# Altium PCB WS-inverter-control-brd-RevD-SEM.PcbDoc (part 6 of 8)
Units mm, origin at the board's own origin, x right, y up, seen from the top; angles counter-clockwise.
Board outline 270 x 105.92 mm, 6 copper layers (Top Layer, Int1 (Sign), Int2 (PWR), Int3 (GND), Int4 (Sign), Bottom Layer), stack 1.509 mm thick; 709 components, 375 nets, 2377 pads, 1332 vias.
Unrouted connection lines stored in the file: 55.
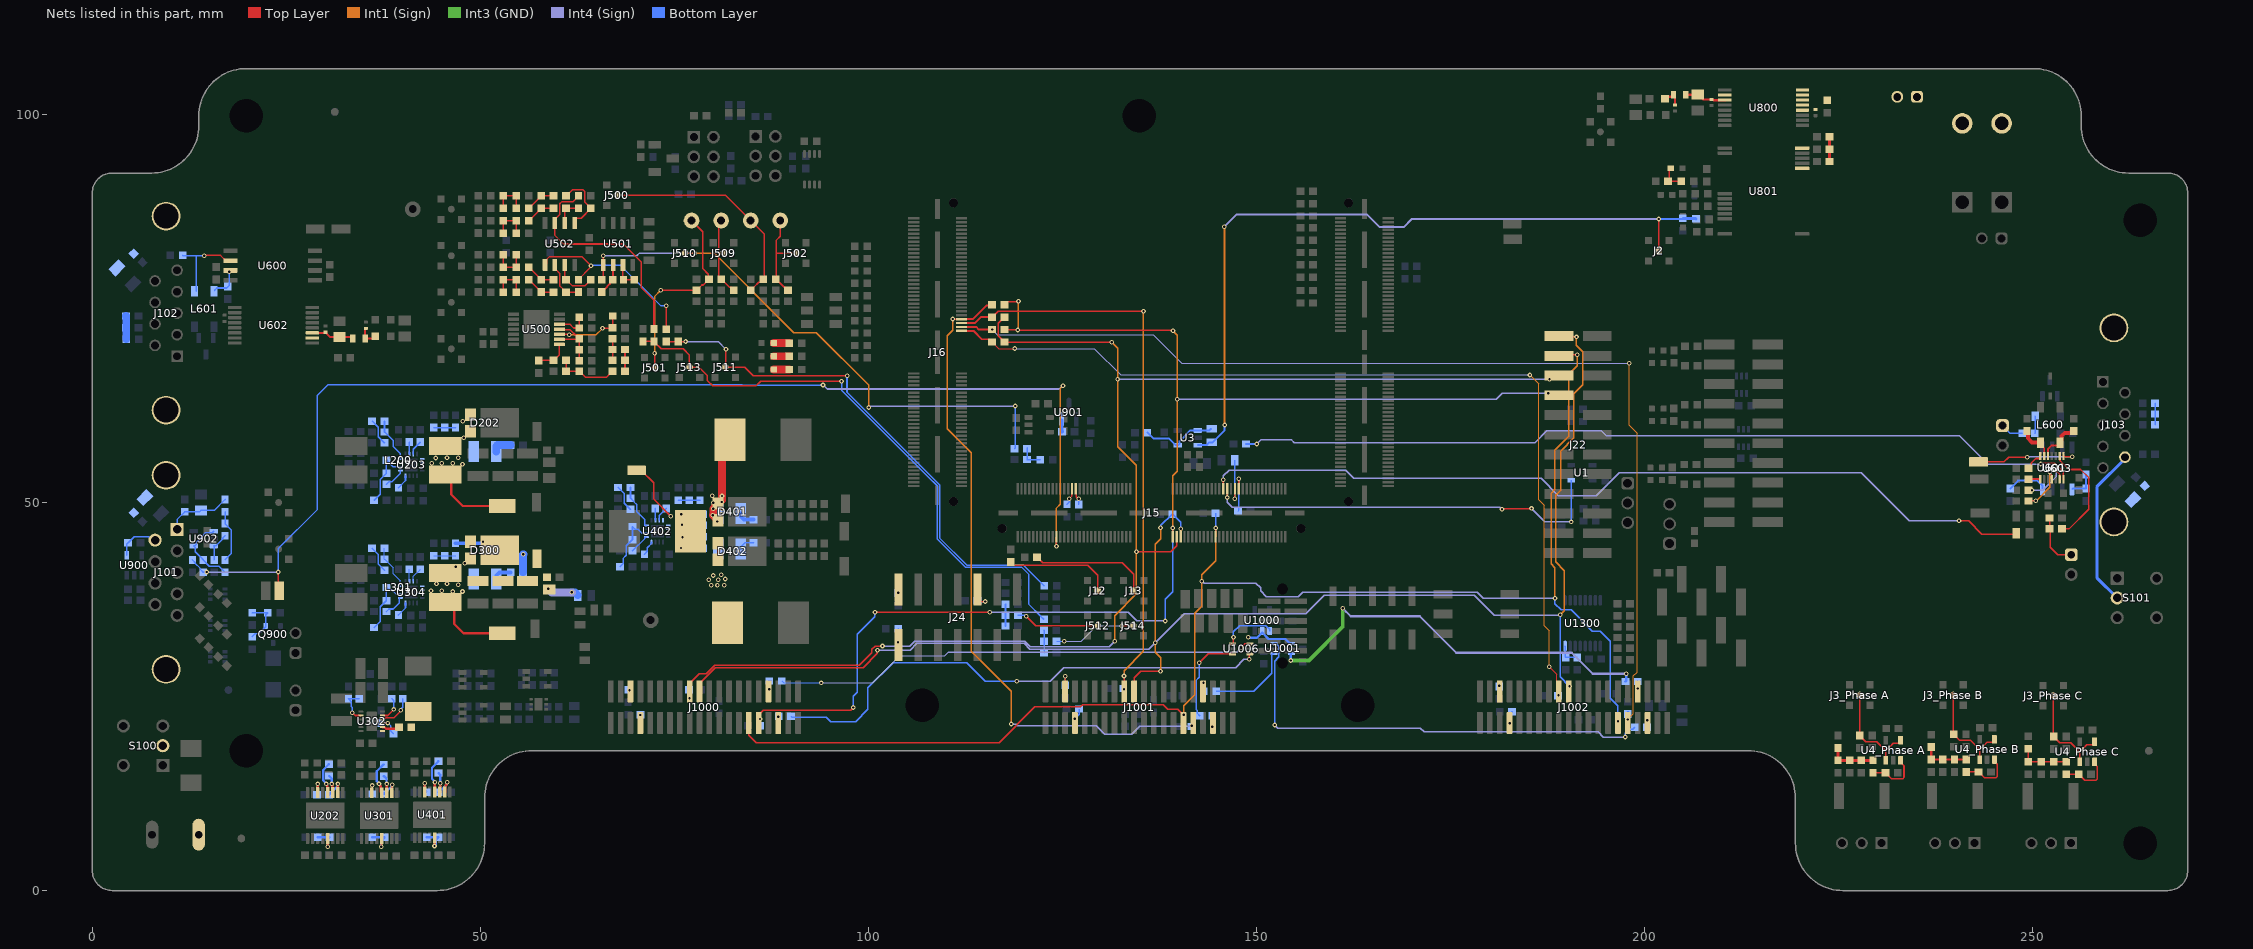
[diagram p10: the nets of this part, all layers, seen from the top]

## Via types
v1: diameter 0.6, hole 0.3, Top Layer to Bottom Layer, tented both sides, 1302 vias
v2: diameter 0.5, hole 0.2, Top Layer to Bottom Layer, 17 vias
v3: diameter 0.6, hole 0.3, Top Layer to Bottom Layer, 12 vias
v4: diameter 0.8, hole 0.5, Top Layer to Bottom Layer, tented both sides, 1 vias

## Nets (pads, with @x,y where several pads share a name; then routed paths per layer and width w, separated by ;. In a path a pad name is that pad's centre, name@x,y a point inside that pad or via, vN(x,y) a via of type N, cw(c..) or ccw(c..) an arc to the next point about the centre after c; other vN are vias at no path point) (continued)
MOTOR_TEMP: C908.1 J15.99 R904.1 TP900.1 | length 158.5
  Top Layer w0.18: v1(124.233,44.346) J15.99@124.233,45.585
  Top Layer w0.2: v1(23.966,41.034) 23.966,38.763 TP900.1@24.093,38.636
  Int1 (Sign) w0.2: v1(124.233,44.346) 124.233,49.278 124.733,49.778 124.733,64.681 v1(125.078,65.026)
  Int4 (Sign) w0.2: v1(14.725,41.034) v1(23.966,41.034) ; v1(94.143,65.136) 94.195,65.136 94.704,64.627 124.57,64.627 124.97,65.026 v1(125.078,65.026)
  Bottom Layer w0.2: C908.1@12.9,42.6 13.275,42.225 13.275,42.143 13.925,41.493 13.925,41.375 R904.1@14.3,41 14.334,41.034 v1(14.725,41.034) ; v1(23.966,41.034) 23.966,44.059 28.953,49.046 28.953,63.758 29.043,63.848 29.043,63.861 30.331,65.148 83.764,65.148 83.776,65.136 v1(94.143,65.136)
NetC5_1: C5.1 J2.1 R9.2 R10jump.2 U3.3 | length 97.2
  Top Layer w0.25: J2.1@201.843,82.436 v1(201.843,86.536)
  Int1 (Sign) w0.25: v1(145.843,85.536) 145.875,85.504 145.875,60.014 v1(145.908,59.982)
  Int4 (Sign) w0.25: v1(145.843,85.536) 147.443,87.136 164.218,87.136 165.871,85.483 168.996,85.483 170.05,86.536 v1(201.843,86.536)
  Bottom Layer w0.25: U3.3@142.443,57.386 143.568,57.386 143.938,57.756 144.348,57.756 145.898,59.307 145.898,59.972 v1(145.908,59.982) ; v1(201.843,86.536) 204.859,86.536 C5.1@204.95,86.628
  Bottom Layer w0.381: C5.1@204.993,86.585 206.6,86.585 R9.2@206.643,86.542
NetC6_2: C6.2 R12.2 R13.1 | length 3.5
  Top Layer w0.2: C6.2@203.4,93.078 203.192,92.87 203.192,91.52 R13.1@203.05,91.378 R12.2@204.75,91.378
"NetC11_Phase A_1": "C11_Phase A.1" "R19_Phase A.1" "R21_Phase A.2" "R22_Phase A.1" "R24_Phase A.2" | length 6.1
  Top Layer w0.4: 224.95,18.378 224.95,16.778 227.95,16.778 229.45,16.778
"NetC11_Phase B_1": "C11_Phase B.1" "R19_Phase B.1" "R21_Phase B.2" "R22_Phase B.1" "R24_Phase B.2" | length 6.1
  Top Layer w0.3: 236.95,18.478 236.95,16.878 238.45,16.878 241.45,16.878
"NetC11_Phase C_1": "C11_Phase C.1" "R19_Phase C.1" "R21_Phase C.2" "R22_Phase C.1" "R24_Phase C.2" | length 6.6
  Top Layer w0.2: 249.45,18.278 249.45,16.578 251.15,16.578 254.35,16.578
"NetC12_Phase A_1": "C12_Phase A.1" "R22_Phase A.2" "U4_Phase A.3" | length 6.8
  Top Layer w0.2: 229.45,15.178 231.05,15.178 231.075,15.178 231.85,14.403 233.274,14.403 233.45,14.579 233.45,16.078 233,16.528 233,16.778
"NetC12_Phase B_1": "C12_Phase B.1" "R22_Phase B.2" "U4_Phase B.3" | length 6.7
  Top Layer w0.2: 241.45,15.278 243.05,15.278 243.075,15.278 243.85,14.503 245.274,14.503 245.45,14.679 245.45,16.278 245.1,16.628 245.1,16.878
"NetC12_Phase C_1": "C12_Phase C.1" "R22_Phase C.2" "U4_Phase C.3" | length 6.7
  Top Layer w0.2: 254.35,14.978 255.95,14.978 255.975,14.978 256.75,14.203 258.174,14.203 258.35,14.379 258.35,15.978 258,16.328 258,16.578
NetC100_1: C100.1 J101.10 J101.11 R100.2
NetC101_1: C101.1 J102.10 J102.11 R101.2
NetC102_1: C102.1 J103.10 J103.11 R102.2
NetC218_1: C218.1 U202.12 | length 4.2
  Top Layer w0.3: v1(30.143,13.736) 30.143,13.682 30.25,13.575 30.25,12.688 U202.12@30.325,12.613
  Bottom Layer w0.3: v1(30.143,13.736) 30.143,13.78 29.75,14.173 29.75,15.538 30.475,16.263 C218.1@30.5,16.263
NetC219_2: C219.2 R242.2 | length 2.6
  Bottom Layer w1: R242.2@52.05,56.55 52.05,57.25 52.2,57.4 52.9,57.4 C219.2@53.9,57.4
NetC226_1: C226.1 C228.1 D202.1 D202.2 L200.4 R242.1
  other v1: 44.243,55.736 45.7,55.783 47.15,55.783 47.843,58.336 47.718,60.475
NetC226_2: C226.2 C228.2 L200.3 TP200.1 U203.13 U203.14 | length 10.1
  Top Layer w0.3: L200.3@45.45,53.6 46.243,52.807 46.243,51.036 47.73,49.55 TP200.1@52.8,49.55
  other v1: 47.7,54.931 43.743,55.036 45.043,55.036 46.452,55.046
NetC235_1: C235.1 R243.1 R247.2 U203.6 | length 8
  Bottom Layer w0.2: R243.1@36.3,50.286 36.325,50.286 37.1,51.061 37.1,52.975 37.875,53.75 R247.2@37.9,53.75 C235.1@37.9,55.45 37.925,55.45 38.3,55.075 38.3,55.05 38.75,54.6 U203.6@39.7,54.6
NetC236_1: C236.1 R244.1 R246.2 | length 2.8
  Bottom Layer w0.2: R246.2@44,59.65 C236.1@45.4,59.65 R244.1@46.8,59.65
NetC237_1: C237.1 C238.1 U203.8 | length 5.8
  Bottom Layer w0.2: C237.1@37.643,60.486 C238.1@37.643,59.086 37.668,59.086 38.768,57.986 38.768,57.206 39.7,56.275 U203.8@39.7,55.6
NetC237_2: C237.2 R251.2 | length 3.5
  Bottom Layer w0.2: C237.2@36.043,60.486 36.068,60.486 36.843,59.711 36.843,58.461 37.618,57.686 R251.2@37.643,57.686
NetC239_1: C239.1 U203.10 | length 1.5
  Bottom Layer w0.2: C239.1@40.843,57.786 40.85,57.78 U203.10@40.85,56.25
NetC310_1: C310.1 U301.12 | length 4.3
  Top Layer w0.3: v1(36.943,13.736) 36.943,13.623 37.147,13.419 37.147,12.728 U301.12@37.282,12.593
  Bottom Layer w0.3: v1(36.943,13.736) 36.943,13.818 36.661,14.1 36.661,15.371 37.532,16.243 C310.1@37.557,16.243
NetC311_2: C311.2 R319.1 U302.3 | length 3.3
  Top Layer w0.2: U302.3@37.39,21.55 37.415,21.575 v1(38.055,21.575)
  Bottom Layer w0.2: R319.1@37.2,21.6 v1@38.055,21.6 ; v1(38.055,21.575) 38.08,21.6 38.48,21.2 38.48,20.52 C311.2@38.8,20.2
NetC312_1: C312.1 U302.2 | length 2.3
  Top Layer w0.3: U302.2@37.39,21.05 37.649,21.05 37.839,20.86 39.31,20.86 C312.1@39.5,21.05
NetC312_2: C312.2 L300.1 U302.1
NetC316_1: C316.1 C331.1 C332.1 C333.1 C334.1 C335.1 D300.3 R311.2 Rjumppre.2 TP301.1 | length 10.1
  Int4 (Sign) w1: v1(58.75,38.875) 59.207,38.418 v1(61.793,38.418)
  Bottom Layer w0.5: R311.2@46.8,44.75 50.157,44.75 v1(50.343,44.936)
  Bottom Layer w1: C316.1@55.5,41 55.5,43.293 v1(55.543,43.336) ; v1(61.793,38.418) 62.187,38.418 62.563,38.042 Rjumppre.2@62.563,38.036
NetC316_2: C316.2 R309.2 | length 2.5
  Bottom Layer w0.5: R309.2@52.05,40.15 52.05,40.6 52.45,41 C316.2@53.9,41
NetC323_1: C323.1 C329.1 D300.1 D300.2 L301.4 R309.1
  other v1: 47.15,39.412 44.343,39.533 45.7,39.525 46.843,41.736 48,42.166
NetC323_2: C323.2 C329.2 L301.3 TP300.1 U304.13 U304.14 | length 10.1
  Top Layer w0.3: L301.3@45.45,37.2 45.643,37.2 46.643,36.2 46.643,34.336 47.83,33.15 TP300.1@52.8,33.15
  other v1: 46.443,38.533 47.7,38.535 43.643,38.633 45.043,38.633
NetC336_1: C336.1 R311.1 R313.2 | length 2.8
  Bottom Layer w0.16: R313.2@44,43.15 R311.1@46.8,43.15
NetC337_1: C337.1 R310.1 R314.2 U304.6 | length 8
  Bottom Layer w0.2: R310.1@36.3,33.886 36.325,33.886 37.1,34.661 37.1,36.575 37.875,37.35 R314.2@37.9,37.35 C337.1@37.9,39.05 38.193,38.757 38.583,38.757 39.14,38.2 U304.6@39.7,38.2
NetC338_1: C338.1 C343.1 U304.8 | length 5.8
  Bottom Layer w0.16: C338.1@37.643,44.086 C343.1@37.643,42.686 37.668,42.686 38.788,41.566 38.788,40.815 39.7,39.903 U304.8@39.7,39.2
NetC338_2: C338.2 R318.2 | length 3.5
  Bottom Layer w0.2: C338.2@36.043,44.086 36.068,44.086 36.843,43.311 36.843,42.061 37.618,41.286 R318.2@37.643,41.286
NetC344_1: C344.1 U304.10 | length 1.5
  Bottom Layer w0.16: C344.1@40.843,41.386 40.85,41.38 U304.10@40.85,39.85
NetC410_1: C410.1 U401.12 | length 4.5
  Top Layer w0.18: U401.12@44.125,12.693 U401.12@44.134,12.702 ; v1@44.134,13.927 v1(44.143,13.936)
  Top Layer w0.3: U401.12@44.134,12.702 v1@44.134,13.927
  Bottom Layer w0.3: v1(44.143,13.936) 44.143,14.018 43.761,14.4 43.761,15.829 44.575,16.643 C410.1@44.6,16.643
NetC411_1: C411.1 C419.1 C430.1 C434.1 L400.2 TP400.1 U402.12 U402.13 U402.14 | length 8.1
  Top Layer w0.2: TP400.1@70.143,54.136 70.743,54.136 72.343,52.536 72.343,50.436 v1(74.543,48.236)
  other v1: 75.843,44.136 76.043,45.536 75.975,47.125 75.876,48.47
NetC411_2: C411.2 C419.2 D401.1 D401.2 L401.2 R421.1 | length 12.3
  Top Layer w1: D401.2@80.23,49.59 80.505,49.865 D401.2@80.62,49.865 ; v1(80.519,47.55) 80.62,47.651 D401.1@80.62,47.735 80.59,47.735 v1(79.952,48.373) 80,48.42 v1(80,49.19) 80.59,49.78 81.143,50.333 v1(81.143,50.836) 81.143,56.343 82.15,57.35 L401.2@82.15,58.1
  other v1: 81.026,48.463 81.117,49.222 80.006,49.95 81.09,50.071 79.888,50.867
NetC412_2: C412.2 R421.2 | length 2.2
  Bottom Layer w0.5: R421.2@83.55,48.6 83.55,48.2 83.95,47.8 C412.2@85.2,47.8
NetC430_2: C430.2 C434.2 D402.1 D402.2 L402.1 R427.1 | length 2.1
  Top Layer w0.2: D402.1@80.62,42.635 80.62,42.65 D402.2@80.62,44.765
  other v1: 79.743,39.336 80.545,39.349 81.443,39.336 79.443,40.036 80.662,40.043 81.543,40.136 80.004,40.596 81.053,40.7
NetC431_2: C431.2 R427.2 | length 2.1
  Bottom Layer w0.2: R427.2@83.55,44 83.55,44.25 84.1,44.8 C431.2@85.2,44.8
NetC432_1: C432.1 R425.1 R428.2 U402.6 | length 8
  Bottom Layer w0.2: R425.1@68,41.736 68.02,41.736 68.395,42.111 68.395,42.799 68.8,43.204 68.8,44.396 68.8,44.425 69.575,45.2 R428.2@69.6,45.2 C432.1@69.6,46.9 69.919,46.581 70.277,46.581 70.788,46.07 71.38,46.07 U402.6@71.4,46.05
NetC433_1: C433.1 R426.1 R430.2 | length 2.8
  Bottom Layer w0.2: R430.2@75.5,50.3 R426.1@78.3,50.3
NetC443_1: C443.1 C444.1 U402.8 | length 5.9
  Bottom Layer w0.2: C443.1@69.343,51.936 C444.1@69.343,50.536 69.368,50.536 69.743,50.161 69.743,50.133 70.143,49.733 70.143,48.836 71.2,47.78 71.2,47.07 71.22,47.05 U402.8@71.4,47.05
NetC443_2: C443.2 R434.2 | length 3.5
  Bottom Layer w0.2: C443.2@67.743,51.936 67.768,51.936 68.543,51.161 68.543,51.133 68.543,49.911 69.318,49.136 R434.2@69.343,49.136
NetC445_1: C445.1 U402.10 | length 1.5
  Bottom Layer w0.2: C445.1@72.543,49.236 72.55,49.23 U402.10@72.55,47.7
NetC500_1: C500.1 C502.2 R550.2 | length 2.8
  Top Layer w0.2: C502.2@67.038,68.311 R550.2@67.038,71.111
NetC500_2: C500.2 C502.1 R501.1 | length 2.8
  Top Layer w0.2: R501.1@68.638,66.911 C502.1@68.638,68.311 C500.2@68.638,69.711
NetC501_1: C501.1 R502.2 U500.1 | length 4
  Top Layer w0.2: C501.1@57.838,68.411 57.901,68.349 59.401,68.349 R502.2@59.438,68.311 59.463,68.311 60.188,69.036 U500.1@60.188,70.361
NetC503_1: C503.1 R500.1 R501.2 R502.1 | length 8
  Top Layer w0.2: R502.1@61.038,68.311 R500.1@61.038,66.911 C503.1@62.744,66.911 62.769,66.911 63.544,66.136 66.238,66.136 67.013,66.911 R501.2@67.038,66.911
NetC506_2: C506.2 R505.1 R506.2 U500.2 U500.4 | length 8.4
  Top Layer w0.2: U500.2@60.188,71.011 62.344,71.011 62.555,71.222 62.344,71.433 62.344,71.486 61.587,72.244 60.256,72.244 U500.4@60.188,72.311 ; R506.2@62.555,71.276 R506.2@62.744,71.086 C506.2@62.744,69.686 R505.1@62.744,68.286
NetC507_1: C507.1 C510.1 R519.2 R520.1 | length 4.9
  Top Layer w0.2: R520.1@52.938,77.111 C510.1@52.938,78.711 R519.2@54.638,78.711 C507.1@54.638,77.111
NetC508_2: C508.2 R513.2 R514.2 | length 3.2
  Bottom Layer w0.2: R514.2@120.443,57.036 C508.2@120.443,55.536 120.468,55.512 122.119,55.512 R513.2@122.144,55.487
NetC509_1: C509.1 R523.2 R524.1 | length 3.9
  Top Layer w0.2: R524.1@56.238,80.311 56.263,80.311 57.838,78.736 C509.1@57.838,78.711 R523.2@59.438,78.711
NetC509_2: C509.2 R518.2 R519.1 | length 3.9
  Top Layer w0.2: R519.1@56.238,78.711 56.263,78.711 57.463,77.511 57.838,77.136 C509.2@57.838,77.111 R518.2@59.438,77.111
NetC510_2: C510.2 C511.2 R524.2 R525.1 | length 4.9
  Top Layer w0.2: R525.1@52.938,81.911 C510.2@52.938,80.311 R524.2@54.638,80.311 C511.2@54.638,81.911
NetC513_1: C513.1 C515.1 R536.2 R537.1 | length 4.9
  Top Layer w0.2: R537.1@52.938,84.711 C515.1@52.938,86.311 R536.2@54.638,86.311 C513.1@54.638,84.711
NetC514_1: C514.1 R542.2 R543.1 | length 3.9
  Top Layer w0.2: R543.1@56.238,87.911 56.263,87.911 57.838,89.486 C514.1@57.838,89.511 R542.2@59.438,89.511
NetC514_2: C514.2 R535.2 R536.1 | length 3.9
  Top Layer w0.2: R536.1@56.238,86.311 56.263,86.311 57.463,87.511 57.463,87.536 C514.2@57.838,87.911 R535.2@59.438,87.911
NetC515_2: C515.2 C520.2 R543.2 R544.1 | length 4.9
  Top Layer w0.2: C515.2@52.938,87.911 R544.1@52.938,89.511 C520.2@54.638,89.511 R543.2@54.638,87.911
NetC528_2: C528.2 R564.1 R565.2 | length 2.8
  Bottom Layer w0.25: C528.2@117.668,34.086 R565.2@117.668,35.486 R564.1@117.668,36.886
NetC531_2: C531.2 R569.1 R570.2 | length 2.9
  Bottom Layer w0.2: R569.1@122.618,33.542 122.643,33.516 R570.2@122.643,32.136 C531.2@122.643,30.636
NetC603_2: C603.2 R602.1 R605.2 | length 2.8
  Bottom Layer w0.2: C603.2@265.8,60.006 R605.2@265.8,62.806
NetC604_2: C604.2 R603.1 R607.2 | length 3
  Bottom Layer w1: R607.2@4.343,74.036 4.368,74.011 R603.1@4.368,71.021
NetC605_2: C605.2 FB600.2 L602.1 | length 3
  Top Layer w0.25: C605.2@35.243,72.436 35.218,72.436 35.143,72.361 L602.1@35.143,71.136 36.368,71.136 36.543,71.311 FB600.2@36.543,71.436
NetC606_1: C606.1 C613.2 L602.2 U602.2 U602.3 | length 5.6
  Top Layer w0.25: U602.3@28.343,71.861 29.918,71.861 29.993,71.936 C613.2@30.043,71.936 ; C613.2@30.052,71.936 30.093,71.936 30.168,71.861 30.168,71.82 30.668,71.32 C606.1@31.843,71.32 33.359,71.32 L602.2@33.543,71.136
NetC800_1: C800.1 C802.2 L800.1 U800.2 U800.3 | length 5.3
  Top Layer w0.3: L800.1@205.343,102.536 205.359,102.552 C802.2@206.843,102.552 207.008,102.552 207.624,101.936 C800.1@208.643,101.936 208.693,101.886 208.886,101.886 208.919,101.853 U800.3@210.35,101.853
NetC801_1: C801.1 FB801.1 L800.2 | length 2.9
  Top Layer w0.3: FB801.1@202.543,102.036 202.543,102.14 202.693,102.29 203.543,102.29 203.743,102.49 L800.2@203.743,102.536 203.943,102.336 C801.1@203.943,101.236
NetC906_1: C906.1 R901.1 U902.3 | length 3.9
  Bottom Layer w0.2: C906.1@15.7,42.6 15.686,42.614 15.686,44.361 U902.3@15.643,44.403 15.893,44.403 16.725,45.235 16.725,45.325 R901.1@17.1,45.7
NetC909_1: C909.1 R901.2 R902.1 | length 6.8
  Bottom Layer w0.2: C909.1@17.1,42.6 17.1,42.625 17.875,43.4 17.875,46.5 17.1,47.275 R901.2@17.1,47.3 R902.1@17.1,48.8
NetC909_2: C909.2 R904.2 U902.1 U902.4 | length 9.4
  Bottom Layer w0.2: U902.4@13.043,44.403 13.198,44.403 13.398,44.603 13.398,44.886 14.615,46.103 15.443,46.103 U902.1@15.643,46.303 ; U902.4@13.061,44.403 13.261,44.203 13.261,43.639 13.9,43 13.925,43 14.3,42.625 R904.2@14.3,42.6 ; R904.2@14.287,42.587 15.075,41.8 16.325,41.8 17.1,41.025 C909.2@17.1,41
NetD1_1: D1.1 R8.2 | length 2
  Top Layer w1: D1.1@87.814,67.136 R8.2@89.814,67.136
NetD2_1: D2.1 R17.2 | length 2
  Top Layer w1: D2.1@87.814,68.836 R17.2@89.814,68.836
NetD3_1: D3.1 R26.2 | length 2
  Top Layer w1: D3.1@87.814,70.536 R26.2@89.814,70.536
NetD602_1: D602.1 R612.2 | length 2.2
  Bottom Layer w0.2: R612.2@250.3,58.9 250.352,58.952 250.352,61.09 D602.1@250.362,61.1
"NetJ3_Phase A_1": "J3_Phase A.1" "R20_Phase A.1" "U4_Phase A.1" "U4_Phase A.4" | length 13.2
  Top Layer w0.2: 227.75,25.178 227.75,19.978 227.75,19.953 228.525,19.178 229.949,19.178 231.1,18.027 ; 231.1,16.778 231.1,18.027 ; 233,19.378 233,19.179 232.8,18.979 232.052,18.979 231.1,18.027
"NetJ3_Phase B_1": "J3_Phase B.1" "R20_Phase B.1" "U4_Phase B.1" "U4_Phase B.4" | length 13.1
  Top Layer w0.2: 239.78,25.178 239.78,20.199 239.843,20.136 239.843,20.111 240.618,19.336 242.042,19.336 243.2,18.179 ; 243.2,16.878 243.2,18.179 ; 245.1,19.478 245.1,19.279 244.9,19.079 244.1,19.079 243.2,18.179
"NetJ3_Phase C_1": "J3_Phase C.1" "R20_Phase C.1" "U4_Phase C.1" "U4_Phase C.4" | length 13.3
  Top Layer w0.2: 252.69,25.111 252.69,19.889 252.743,19.836 252.743,19.811 253.518,19.036 254.942,19.036 256.1,17.879 ; 256.1,16.578 256.1,17.879 ; 258,19.178 258,18.979 257.8,18.779 257,18.779 256.1,17.879
NetJ12_1: J12.1 R7.1 | length 13.9
  Top Layer w0.18: R7.1@118.343,42.336 118.343,42.311 118.728,41.926 128.253,41.926 129.563,40.616 J12.1@129.563,38.636
NetJ13_1: J13.1 R18.1 | length 15.5
  Top Layer w0.18: R18.1@121.743,42.936 121.768,42.936 122.498,42.206 132.743,42.206 134.199,40.75 J13.1@134.199,38.636
NetJ15_26: J15.26 R59.1 | length 5.5
  Top Layer w0.18: J15.26@147.733,51.757 v1(147.733,53.07)
  Bottom Layer w0.18: R59.1@147.642,48.898 147.733,48.99 v1(147.733,53.07)
NetJ15_90: J15.90 Rjldc1.1 | length 2.2
  Top Layer w0.2: J15.90@126.733,51.757 126.786,51.704 126.786,50.746 127.053,50.479 v1(127.112,50.479)
  Bottom Layer w0.2: Rjldc1.1@127.112,49.756 v1(127.112,50.479)
NetJ15_92: J15.92 Rjldc2.1 | length 2.3
  Top Layer w0.2: v1(125.894,50.493) 126.228,50.828 126.228,51.752 J15.92@126.233,51.757
  Bottom Layer w0.2: Rjldc2.1@125.589,49.77 125.894,50.075 v1(125.894,50.493)
NetJ24_5: J24.5 R14.2 | length 3.3
  Top Layer w0.18: J24.5@114.053,38.786 114.053,37.646 114.463,37.236 v1(115.043,37.236)
  Bottom Layer w0.2: R14.2@114.043,37.326 114.133,37.236 v1(115.043,37.236)
NetJ24_13: J24.13 R15.2 | length 0.1
  Top Layer w0.2: v1(103.843,38.37) J24.13@103.879,38.405
NetJ24_14: J24.14 R16.1 | length 1.7
  Top Layer w0.2: J24.14@103.821,32.001 v1(103.821,32.011)
  Bottom Layer w0.2: v1(103.821,32.011) 103.843,32.033 R16.1@103.843,33.736
NetJ100_1: J100.1 S100.2
NetJ103_9: J103.9 S101.2 | length 20.7
  Bottom Layer w0.4: S101.2@260.92,37.696 258.3,40.316 258.3,52.012 261.92,55.633 J103.9@261.92,55.845
NetJ500_1: J500.1 R552.2 R554.2 TP500.1 | length 29.2
  Top Layer w0.2: J500.1@67.589,89.589 81.58,89.589 TP500.1@84.833,86.336 86.588,84.581 86.588,78.891 86.075,78.378 85.875,78.378 85.25,77.753 85.25,77.728 84.875,77.353 R554.2@84.85,77.353
NetJ501_1: J501.1 R553.2 R555.2 TP501.1 | length 25.6
  Top Layer w0.2: v1(72.448,69.242) 72.461,69.229 72.461,67.376 J501.1@72.473,67.363 ; v1(73.243,77.336) 77.834,77.336 R555.2@77.85,77.353 77.875,77.353 78.55,78.028 78.725,78.028 79.05,78.353 79.05,78.378 R553.2@79.425,78.753 ; TP501.1@77.213,86.336 78.65,84.9 78.65,80.136 79.376,79.411 79.376,78.828 R553.2@79.45,78.753
  Int1 (Sign) w0.2: v1(72.448,69.242) 72.448,76.542 v1(73.243,77.336)
NetJ502_1: J502.1 R558.1 R560.2 TP502.1 | length 12.5
  Top Layer w0.2: TP502.1@88.643,86.336 88.643,84.299 88.153,83.809 88.153,82.151 ; R558.1@89.65,77.353 89.275,77.728 89.168,77.728 88.518,78.378 88.425,78.378 R560.2@88.05,78.753 88.153,78.856 88.153,82.151 ; J502.1@90.643,82.136 88.167,82.136 88.153,82.151
NetJ509_1: J509.1 R559.1 R561.2 TP503.1 | length 10.7
  Top Layer w0.2: TP503.1@81.023,86.336 80.698,86.011 80.698,82.149 ; R561.2@81.05,78.753 80.698,79.105 80.698,82.149 ; R561.2@81.075,78.753 82.1,77.728 82.275,77.728 R559.1@82.65,77.353 ; J509.1@81.343,82.136 81.33,82.149 80.698,82.149
NetJ510_1: J510.1 R510.2 R514.1 U501.1 | length 73.2
  Top Layer w0.2: R510.2@65.638,78.711 65.833,78.906 U501.1@65.833,80.611 v1(65.833,81.801) ; J510.1@76.343,82.136 v1(77.643,82.136)
  Int1 (Sign) w0.2: v1(77.643,82.136) 80.143,82.136 90.393,71.886 93.293,71.886 100.043,65.136 v1(100.043,62.236)
  Int4 (Sign) w0.2: v1(65.833,81.801) 70.164,81.801 70.499,82.136 v1(77.643,82.136) ; v1(100.043,62.236) 100.151,62.236 100.308,62.393 118.9,62.393 v1(118.943,62.436)
  Bottom Layer w0.2: R514.1@118.843,56.936 R514.1@118.943,57.036 ; R514.1@118.943,57.136 v1(118.943,62.436)
NetJ511_1: J511.1 R527.1 R528.1 R562.1 | length 68.5
  Top Layer w0.2: R527.1@73.943,70.736 v1(76.443,70.736) ; v1(81.643,69.731) 81.593,69.681 81.593,67.486 J511.1@81.543,67.436 84.068,67.436 85.168,66.336 97.268,66.336 v1(97.28,66.324)
  Int4 (Sign) w0.2: v1(76.443,70.736) 80.637,70.736 v1(81.643,69.731)
  Bottom Layer w0.2: v1(97.28,66.324) 97.243,66.286 97.243,64.209 109.043,52.409 109.043,52.401 109.177,52.267 109.177,45.427 112.667,41.936 119.955,41.936 122.633,39.258 R528.1@122.658,39.258
NetJ512_1: J512.1 R565.1 | length 10.8
  Top Layer w0.18: v1(120.343,35.336) 121.543,34.136 J512.1@129.543,34.136
  Bottom Layer w0.18: R565.1@119.268,35.486 120.08,35.486 120.23,35.336 v1(120.343,35.336)
NetJ513_1: J513.1 R546.1 R547.1 R566.1 | length 75.2
  Top Layer w0.2: R566.1@70.957,70.757 R546.1@72.375,70.757 72.375,70.732 73.311,69.797 76.127,69.797 76.943,68.981 J513.1@76.943,67.436 78.166,67.436 79.243,66.359 79.243,65.736 79.943,65.036 85.524,65.036 86.124,65.636 v1(96.543,65.636)
  Bottom Layer w0.2: v1@96.577,65.636 96.577,64.443 107.783,53.236 107.792,53.236 108.743,52.285 108.743,52.277 108.877,52.143 108.877,45.303 112.543,41.636 119.781,41.636 120.645,40.772 120.645,36.914 122.218,35.342 122.218,35.317 122.593,34.942 R547.1@122.618,34.942
NetJ514_1: J514.1 R570.1 | length 10.7
  Top Layer w0.18: v1(132.651,34.087) 132.675,34.112 134.102,34.112 J514.1@134.127,34.136
  Int4 (Sign) w0.16: v1(125.243,32.136) 127.443,32.136 129.394,34.087 v1(132.651,34.087)
  Bottom Layer w0.16: R570.1@124.243,32.136 v1(125.243,32.136)
NetJ600_1: J600.1 R612.1 | length 3
  Bottom Layer w0.2: J600.1@246.143,59.906 247.15,58.9 R612.1@248.7,58.9
NetJ601_1: J601.1 R618.1 R619.1 | length 6.9
  Top Layer w0.2: R619.1@252.2,48 R618.1@252.2,46.6 252.307,46.493 252.307,44.218 253.255,43.27 J601.1@255,43.27
NetJ1000_6: J1000.6 R1000.1 | length 0.3
  Top Layer w0.18: v1(69.217,25.786) J1000.6@69.349,25.653
  Bottom Layer w0.18: v1(69.217,25.786) R1000.1@69.217,25.904
NetJ1000_7: J1000.7 R1003.2 | length 1.1
  Top Layer w0.18: J1000.7@70.619,21.588 v1(70.619,22.612)
  Top Layer w0.25: J1000.7@70.619,21.588 J1000.7@70.643,21.613
  Bottom Layer w0.18: v1(70.619,22.612) R1003.2@70.643,22.636
NetJ1000_34: J1000.34 R1006.1 | length 1.5
  Top Layer w0.18: J1000.34@87.206,25.922 v1(87.229,25.945)
  Top Layer w0.25: J1000.34@87.129,25.653 J1000.34@87.129,25.922
  Bottom Layer w0.18: v1(87.229,25.945) R1006.1@87.229,26.999
  Bottom Layer w0.25: R1006.1@87.129,26.899 R1006.1@87.229,26.999
NetJ1000_35: J1000.35 R1009.2 | length 1.2
  Top Layer w0.18: J1000.35@88.399,21.588 v1(88.399,22.408)
  Top Layer w0.25: J1000.35@88.343,21.236 J1000.35@88.343,21.588
  Bottom Layer w0.18: v1(88.399,22.408) R1009.2@88.45,22.458
NetJ1001_6: J1001.6 R1001.1 | length 3.1
  Top Layer w0.18: J1001.6@125.349,25.653 125.356,25.66 v1(125.356,27.617)
  Bottom Layer w0.18: R1001.1@125.349,26.454 125.356,26.46 v1(125.356,27.617)
NetJ1001_7: J1001.7 R1004.2 | length 2
  Top Layer w0.18: v1(126.593,22.136) 126.593,21.614 J1001.7@126.619,21.588
  Bottom Layer w0.18: v1(126.593,22.136) 127.143,22.686 R1004.2@127.143,23.386
NetJ1001_34: J1001.34 R1007.1 | length 1.4
  Top Layer w0.18: J1001.34@143.175,26.482 v1(143.175,26.753)
  Bottom Layer w0.18: v1(143.175,26.753) 143.175,25.707 R1007.1@143.229,25.653
NetJ1001_35: J1001.35 R1010.2 | length 1.2
  Top Layer w0.18: v1(144.299,21.118) J1001.35@144.301,21.116
  Top Layer w0.25: J1001.35@144.332,21.147 J1001.35@144.343,21.136
  Bottom Layer w0.18: v1(144.299,21.118) R1010.2@144.299,22.329
NetJ1002_6: J1002.6 R1002.1 | length 0.1
  Bottom Layer w0.2: R1002.1@181.271,26.3 v1(181.271,26.375)
NetJ1002_7: J1002.7 R1005.2 | length 1.6
  Bottom Layer w0.2: v1(182.631,21.573) 182.631,22.725 R1005.2@182.943,23.036
NetJ1002_34: J1002.34 R1008.1 | length 1
  Top Layer w0.2: J1002.34@199.129,25.653 199.129,25.647 J1002.34@199.212,25.564
  Bottom Layer w0.2: v1(199.143,26.036) R1008.1@199.143,26.936
NetJ1002_35: J1002.35 R1011.2 | length 0.9
  Bottom Layer w0.2: R1011.2@200.343,21.036 v1(200.343,21.936)
NetL600_3: L600.3 R600.1 U601.13 | length 4.8
  Top Layer w0.2: L600.3@251.05,57.725 251.05,57.5 251.496,57.054 251.5,57.054 U601.13@251.5,56
  Top Layer w0.5: R600.1@249.3,59.2 249.406,59.094 249.406,58.273 249.955,57.725 L600.3@251.05,57.725
NetL600_4: L600.4 R608.1 U601.12 | length 5.6
  Top Layer w0.25: U601.12@252,56 252,56.886 252.438,57.324 253.225,57.324 253.55,57.649 L600.4@253.55,57.725
  Top Layer w0.5: L600.4@253.55,57.725 253.75,57.925 253.75,58.544 254.156,58.95 255.075,58.95 255.3,59.175 R608.1@255.3,59.2
NetL601_1: L601.1 R610.1 U600.6 | length 11.1
  Top Layer w0.2: v1(14.419,81.813) 14.443,81.836 16.528,81.836 17.193,81.171 U600.6@17.793,81.171
  Bottom Layer w0.2: R610.1@11.643,81.836 11.667,81.813 13.412,81.813 ; L601.1@13.393,77.211 13.393,81.794 13.412,81.813 ; v1(14.419,81.813) 13.412,81.813
NetL601_2: L601.2 R601.1 U600.7 | length 4.1
  Top Layer w0.2: v1(17.643,79.751) U600.7@17.718,79.826
  Bottom Layer w0.2: L601.2@15.793,77.282 15.793,77.386 16.043,77.636 17.323,77.636 17.643,77.957 v1(17.643,79.751)
NetQ900_1: Q900.1 R905.1 R906.2 R907.2 | length 6.2
  Bottom Layer w0.2: R906.2@20.6,32.7 20.6,32.72 20.975,33.095 21.445,33.095 22.35,34 Q900.1@22.35,34.1 22.35,35.55 R907.2@22.6,35.8 R905.1@20.6,35.8
NetR10_1: R10.1 R10jump.1 U3.1 U3.4 | length 9.9
  Bottom Layer w0.25: R10.1@135.943,59.002 135.968,59.002 136.742,58.228 138.751,58.228 139.593,57.386 139.929,57.386 140.104,57.561 140.104,57.915 141.475,59.286 143.943,59.286 R10jump.1@144.143,59.486
NetR235_1: R235.1 U202.14 | length 2.5
  Top Layer w0.3: U202.14@29.025,12.613 29.034,12.622 29.034,13.727 v1(29.043,13.736)
  Bottom Layer w0.3: R235.1@28.95,12.363 29.043,12.456 v1(29.043,13.736)
NetR236_1: R236.1 R238.2 U202.5 | length 3.9
  Top Layer w0.3: U202.5@30.325,6.713 30.334,6.704 30.334,5.646 v1(30.343,5.636)
  Bottom Layer w0.3: R236.1@29.057,6.863 R238.2@30.557,6.863 30.343,6.649 v1(30.343,5.636)
NetR239_2: R239.2 U202.11 | length 2.3
  Top Layer w0.3: v1(30.843,13.736) 30.843,13.682 30.9,13.625 30.9,12.688 U202.11@30.975,12.613
  Bottom Layer w0.3: R239.2@30.5,14.749 30.518,14.749 30.843,14.424 v1(30.843,13.736)
NetR240_2: R240.2 U202.10 | length 3
  Top Layer w0.3: U202.10@31.625,12.613 31.634,12.622 31.634,13.727 v1(31.643,13.736)
  Bottom Layer w0.3: R240.2@30.5,12.363 30.525,12.363 31.586,13.424 31.586,13.679 v1(31.643,13.736)
NetR245_1: R245.1 U203.4 | length 1.9
  Bottom Layer w0.2: R245.1@39.443,51.886 39.443,51.911 40.35,52.818 U203.4@40.35,53.45
NetR249_2: R249.2 U203.5 | length 2.7
  Bottom Layer w0.2: R249.2@37.9,52.35 38.195,52.645 38.583,52.645 39.7,53.762 U203.5@39.7,54.1
NetR250_2: R250.2 U203.11 | length 1.9
  Bottom Layer w0.2: U203.11@41.35,56.25 41.35,56.868 42.243,57.761 R250.2@42.243,57.786
NetR300_1: R300.1 U301.14 | length 2.1
  Top Layer w0.18: U301.14@35.982,12.593 36.034,12.644 36.034,13.491 v1(36.085,13.543)
  Bottom Layer w0.18: R300.1@36.057,12.443 36.085,12.471 v1(36.085,13.543)
NetR301_1: R301.1 R303.2 U301.5 | length 4
  Top Layer w0.3: v1(37.243,5.636) 37.263,5.656 37.263,6.673 U301.5@37.282,6.693
  Bottom Layer w0.3: R301.1@36.057,6.843 R303.2@37.632,6.843 ; v1(37.243,5.636) 37.243,6.429 37.307,6.493 37.307,6.518 R303.2@37.632,6.843 ; R303.2@37.657,6.843 R303.2@37.632,6.843
NetR304_2: R304.2 U301.11 | length 2.3
  Top Layer w0.3: U301.11@37.932,12.593 37.938,12.598 37.938,13.731 v1(37.943,13.736)
  Bottom Layer w0.3: R304.2@37.557,14.743 37.582,14.743 37.907,14.418 37.907,13.772 v1(37.943,13.736)
NetR305_2: R305.2 U301.10 | length 2.7
  Top Layer w0.3: U301.10@38.582,12.593 38.613,12.623 38.613,13.606 v1(38.643,13.636)
  Bottom Layer w0.3: R305.2@37.557,12.443 37.582,12.443 38.586,13.446 38.586,13.579 v1(38.643,13.636)
NetR307_1: R307.1 R308.2 U302.8 | length 4.6
  Top Layer w0.2: v1(33.505,22.92) 33.875,22.55 U302.8@34.61,22.55
  Bottom Layer w0.2: v1(33.505,22.92) 33.505,23.571 33.37,23.705 33.37,24.33 R307.1@33,24.7 R308.2@34.4,24.7
NetR312_1: R312.1 U304.4 | length 1.9
  Bottom Layer w0.2: R312.1@39.443,35.486 39.443,35.511 40.35,36.418 U304.4@40.35,37.05
NetR316_2: R316.2 U304.5 | length 2.9
  Bottom Layer w0.2: R316.2@37.9,35.95 38.225,36.275 38.76,36.275 39.55,37.065 39.55,37.67 39.58,37.7 U304.5@39.7,37.7
NetR317_2: R317.2 U304.11 | length 1.9
  Bottom Layer w0.16: U304.11@41.35,39.85 41.35,40.468 42.243,41.361 R317.2@42.243,41.386
NetR320_2: R320.2 U302.5 | length 3.2
  Top Layer w0.2: U302.5@37.39,22.55 38.057,22.55 v1(38.843,23.336)
  Bottom Layer w0.2: R320.2@38.6,24.7 38.843,24.457 v1(38.843,23.336)
NetR321_2: R321.2 U302.4 | length 4.5
  Top Layer w0.2: U302.4@37.39,22.05 37.575,22.05 37.6,22.075 37.6,22.108 37.729,22.236 38.836,22.236 39.743,23.144 v1(39.743,23.236)
  Bottom Layer w0.2: v1(39.743,23.236) 39.743,23.345 40,23.601 R321.2@40,24.7
NetR400_1: R400.1 U401.14 | length 2.5
  Top Layer w0.18: U401.14@42.825,12.693 U401.14@42.834,12.702 ; v1@42.834,13.827 v1(42.843,13.836)
  Top Layer w0.3: U401.14@42.834,12.702 v1@42.834,13.827
  Bottom Layer w0.18: v1(42.843,13.836) 42.843,12.9 R400.1@43.1,12.643
NetR402_1: R402.1 R406.2 U401.5 | length 3.9
  Top Layer w0.3: v1(44.082,5.729) 44.104,5.751 44.104,6.771 U401.5@44.125,6.793
  Bottom Layer w0.3: R402.1@43.1,6.843 R406.2@44.575,6.843 ; v1(44.082,5.729) 44.082,5.784 44.25,5.951 44.25,6.518 R406.2@44.575,6.843 ; R406.2@44.6,6.843 R406.2@44.575,6.843
NetR410_2: R410.2 U401.11 | length 2.6
  Top Layer w0.18: U401.11@44.775,12.693 U401.11@44.809,12.727 ; v1@44.809,13.802 v1(44.843,13.836)
  Top Layer w0.3: U401.11@44.809,12.727 v1@44.809,13.802
  Bottom Layer w0.3: R410.2@44.6,15.143 44.843,14.9 v1(44.843,13.836)
NetR416_2: R416.2 U401.10 | length 3.2
  Top Layer w0.3: U401.10@45.425,12.693 45.5,12.768 45.5,13.539 45.686,13.725 45.686,13.879 v1(45.743,13.936)
  Bottom Layer w0.3: R416.2@44.6,12.643 44.625,12.643 45.686,13.704 45.686,13.879 v1(45.743,13.936)
NetR429_1: R429.1 U402.4 | length 1.9
  Bottom Layer w0.2: R429.1@71.143,43.336 71.513,43.707 71.513,44.183 72.05,44.72 U402.4@72.05,44.9
NetR432_2: R432.2 U402.5 | length 2.6
  Bottom Layer w0.2: R432.2@69.6,43.8 69.625,43.8 71.2,45.375 71.2,45.53 71.22,45.55 U402.5@71.4,45.55
NetR433_2: R433.2 U402.11 | length 1.9
  Bottom Layer w0.2: U402.11@73.05,47.7 73.05,48.318 73.943,49.211 R433.2@73.943,49.236
NetR507_1: R507.1 R551.2 U500.3 | length 8.7
  Top Layer w0.2: U500.3@60.188,71.661 61.418,71.661 v1(61.443,71.636) ; v1(65.743,72.436) 66.963,72.436 R551.2@67.038,72.511 67.041,72.514 67.041,74.034 R507.1@67.043,74.036
  Int1 (Sign) w0.2: v1(61.443,71.636) 64.943,71.636 v1(65.743,72.436)
NetR508_2: R508.2 R509.2 U500.5 | length 4.2
  Top Layer w0.2: U500.5@60.188,72.961 61.542,72.961 62.017,72.486 R509.2@62.744,72.486 R508.2@62.744,73.886
NetR510_1: R510.1 R511.1 U501.2 | length 4.1
  Top Layer w0.25: R510.1@65.638,77.111 65.638,77.136 65.988,77.486 66.013,77.486 66.688,78.161 66.688,78.361 67.103,78.776 U501.2@67.103,80.611
NetR512_1: R512.1 R516.2 U501.3 | length 3.3
  Top Layer w0.2: U501.3@68.373,80.611 68.373,78.776 R512.1@68.438,78.711 R516.2@69.838,78.711
NetR517_1: R517.1 R518.1 U502.2 | length 5.7
  Top Layer w0.2: U502.2@59.603,80.611 59.603,80.136 60.238,79.501 60.238,77.901 60.638,77.501 60.638,77.486 61.013,77.111 R517.1@62.638,77.111
NetR517_2: R517.2 R527.2 U502.1 | length 24.5
  Top Layer w0.2: U502.1@58.333,80.611 58.533,80.811 58.533,81.327 58.893,81.686 63.064,81.686 v1(64.25,80.5) 64.173,80.423 64.173,80.271 62.638,78.736 R517.2@62.638,78.711 ; R527.2@73.943,72.336 v1(73.943,75.336)
  Bottom Layer w0.2: v1(64.25,80.5) 64.296,80.546 68.057,80.546 71.263,77.34 ; 71.263,77.34 73.267,75.336 v1(73.943,75.336)
NetR523_1: R523.1 R529.2 U502.3 | length 5.8
  Top Layer w0.2: U502.3@60.873,80.611 60.873,78.876 R523.1@61.038,78.711 61.063,78.711 61.863,77.911 63.463,77.911 64.238,78.686 R529.2@64.238,78.711
NetR534_1: R534.1 R535.1 U502.6 | length 3.6
  Top Layer w0.2: U502.6@60.873,86.011 60.873,87.746 R535.1@61.038,87.911 R534.1@62.638,87.911
NetR534_2: R534.2 R546.2 U502.7 | length 29.1
  Top Layer w0.2: R534.2@62.638,89.511 62.638,89.486 61.888,88.736 60.467,88.736 60.238,88.508 60.238,87.121 59.603,86.486 U502.7@59.603,86.011 59.603,84.41 60.702,83.311 64.635,83.311 68.413,83.311 70.738,80.986 70.738,77.69 72.375,76.053 R546.2@72.375,72.357
NetR542_1: R542.1 R548.2 U502.5 | length 8.5
  Top Layer w0.2: R542.1@61.038,89.511 61.063,89.511 61.863,90.311 63.235,90.311 63.463,90.083 63.463,88.711 64.238,87.936 R548.2@64.238,87.911 64.238,87.886 62.987,86.635 62.343,86.635 62.143,86.435 U502.5@62.143,86.011
NetR604_2: R604.2 U601.1 | length 1.5
  Top Layer w0.25: R604.2@249.5,53 U601.1@251,53
NetR606_2: R606.2 U601.14 | length 2.5
  Top Layer w0.2: R606.2@249.5,54.4 249.816,54.716 249.816,55.058 250.426,55.667 250.95,55.667 251,55.717 U601.14@251,56
NetR609_2: R609.2 U601.4 | length 6.5
  Top Layer w0.2: R609.2@249.5,50.2 249.536,50.236 v1(250.443,50.236) ; v1(252.243,53.936) 252.243,53.828 252.45,53.621 252.45,53.05 U601.4@252.5,53
  Int1 (Sign) w0.2: v1(250.443,50.236) 250.528,50.236 252.243,51.951 v1(252.243,53.936)
NetR613_1: R613.1 R614.2 U603.1 | length 3.6
  Bottom Layer w0.2: U603.1@255.105,51.7 255.205,51.8 R614.2@256.9,51.8 R613.1@256.9,53.6
NetR615_2: R615.2 U603.4 | length 5.3
  Bottom Layer w0.25: R615.2@247.15,51.8 248.159,52.809 250.637,52.809 251.096,52.35 251.12,52.35 251.295,52.175 U603.4@251.295,51.7
NetR616_2: R616.2 U601.7 | length 109.6
  Top Layer w0.2: v1(251.08,54.953) 251.156,55.029 252.95,55.029 253.95,54.03 253.95,53.05 U601.7@254,53
  Int4 (Sign) w0.2: v1(150.043,57.536) 150.564,58.057 154.523,58.057 154.866,57.714 185.889,57.714 187.411,59.236 194.48,59.236 195.088,58.628 240.566,58.628 244.241,54.953 v1(251.08,54.953)
  Bottom Layer w0.2: R616.2@148.643,57.536 v1(150.043,57.536)
NetR617_2: R617.2 U601.6 | length 6.4
  Top Layer w0.2: R617.2@249.5,51.6 249.931,51.6 v1(249.95,51.581) ; v1(253.043,54.136) 253.043,54.113 253.493,53.663 253.493,53.007 U601.6@253.5,53
  Int4 (Sign) w0.2: v1(249.95,51.581) 251.326,51.581 253.043,53.298 v1(253.043,54.136)
NetR618_2: R618.2 U601.9 | length 13.8
  Top Layer w0.2: U601.9@253.5,56 253.55,55.95 253.55,55.389 254.686,54.253 256.205,54.253 257.243,53.215 257.243,51.736 257.243,49.125 254.718,46.6 R618.2@253.8,46.6
NetR900_1: R900.1 U901.2 | length 1.5
  Bottom Layer w0.5: U901.2@124.893,60.586 124.918,60.561 124.918,59.161 R900.1@124.943,59.136
NetR1303_2: R1303.2 R1304.2 U1300.8 | length 3
  Bottom Layer w0.2: U1300.8@189.775,31.5 189.765,31.49 189.775,31.481 189.775,30.105 R1304.2@189.843,30.036 189.846,30.039 191.323,30.039 R1303.2@191.326,30.042
NetTP602_1: TP602.1 U601.8 | length 13.6
  Top Layer w0.2: TP602.1@243.043,55.236 246.338,55.236 246.938,55.836 v1(249.343,55.836) ; U601.8@254,56 254,55.95 254.05,55.9 v1(255.146,55.9)
  Int4 (Sign) w0.2: v1(249.343,55.836) 249.375,55.868 255.115,55.868 v1(255.146,55.9)
NetU1000_1: U1000.1 U1006.4 | length 7
  Top Layer w0.18: U1006.4@146.918,31.786 146.933,31.786 147.043,31.896 v1(147.043,32.636)
  Bottom Layer w0.18: v1(147.043,32.636) 147.043,33.331 147.84,34.128 151.204,34.128 151.694,33.638 U1000.1@151.694,33.438
NetU1000_2: U1000.2 U1001.4 | length 6.5
  Bottom Layer w0.3: v1(148.943,32.636) 149.001,32.579 149.184,32.579 149.186,32.578 150.084,32.578 150.744,33.238 151.576,32.406 153.726,32.406 154.294,31.838 U1001.4@154.519,31.838
nFLT1_H: J15.55 J22.1 J1000.20 J1001.20 J1002.20 R1027.2 | length 199.1
  Top Layer w0.18: J1000.20@78.239,25.653 78.239,26.681 80.295,28.736 99.317,28.736 101.13,30.549 101.13,30.927 v1(101.163,30.961) ; J1001.20@134.239,25.653 134.239,27.387 135.088,28.236 v1(137.643,28.236) ; J15.55@140.233,45.585 v1(140.233,46.626) ; J22.1@188.993,71.436 189.093,71.336 v1(191.243,71.336)
  Int1 (Sign) w0.18: v1(137.643,28.236) 137.643,29.985 136.943,30.685 v1(136.943,31.936) 136.943,44.636 137.643,45.336 v1(137.643,46.736) ; v1(189.143,35.536) 189.652,36.046 189.652,41.227 188.543,42.336 188.543,50.929 189.189,51.576 189.189,56.622 190.919,58.352 190.919,64.041 192.043,65.165 192.043,69.443 191.243,70.243 v1(191.243,71.336)
  Int4 (Sign) w0.18: v1(101.163,30.961) 105.368,30.961 106.243,31.836 120.069,31.836 120.794,31.111 136.118,31.111 v1(136.943,31.936) 140.683,35.676 156.383,35.676 158.743,38.036 178.043,38.036 180.633,35.446 188.746,35.446 188.756,35.456 189.063,35.456 v1(189.143,35.536)
  Bottom Layer w0.18: v1(137.643,46.736) 137.704,46.798 137.704,47.037 139.158,48.491 R1027.2@139.183,48.491 139.208,48.491 139.593,48.106 139.593,48.081 140.233,47.441 v1(140.233,46.626) ; v1(189.143,35.536) 189.143,27.536 v1(190.343,26.336)
nFLT1_L: J15.37 J22.3 J1000.29 J1001.29 J1002.29 R1030.2 | length 192.6
  Top Layer w0.18: J1000.29@84.589,21.588 84.589,19.991 85.553,19.026 116.833,19.026 121.463,23.656 127.315,23.656 127.595,23.936 137.999,23.936 138.599,23.336 139.868,23.336 140.569,22.635 v1(140.646,22.635) ; J15.37@144.733,45.585 144.741,45.593 144.741,46.713 v1(144.748,46.721) ; J22.3@188.993,68.896 189.133,69.036 v1(191.343,69.036)
  Int1 (Sign) w0.18: v1(140.646,22.635) 140.646,23.839 142.043,25.236 142.043,35.736 142.943,36.636 v1(142.943,39.836) 142.943,40.682 144.757,42.496 v1@144.757,46.712 ; v1(188.469,37.659) 188.469,41.59 187.963,42.096 187.963,51.17 188.469,51.675 188.469,56.722 190.277,58.531 190.277,66.526 191.343,67.592 v1(191.343,69.036)
  Int4 (Sign) w0.18: v1(142.943,39.836) 143.001,39.836 143.259,39.579 149.937,39.579 150.534,38.982 150.534,38.602 151.291,37.845 155.402,37.845 155.993,38.436 178.443,38.436 179.22,37.659 v1(188.469,37.659)
  Bottom Layer w0.18: R1030.2@144.743,48.636 144.748,48.631 v1(144.748,46.721) ; v1(188.469,37.659) 188.469,36.957 189.275,36.151 190.542,36.151 193.257,33.436 194.307,33.436 195.605,32.138 195.605,24.781 196.589,23.798 v1(196.589,21.791)
nFLT2_H: J15.57 J22.5 J1000.18 R1019.1 R1034.2 R1036.2 | length 181.1
  Top Layer w0.18: J1000.18@76.969,25.653 76.969,26.681 78.225,27.936 79.099,27.936 80.179,29.016 98.823,29.016 100.464,30.657 100.464,31.074 100.891,31.501 v1(101.811,31.501) ; R1034.2@117.543,73.884 117.518,73.884 116.738,73.104 116.738,71.464 117.133,71.069 117.566,70.636 v1(131.343,70.636) ; v1(134.543,43.636) 138.936,43.636 139.741,44.442 J15.57@139.741,45.577
  Top Layer w0.2: J1000.18@76.811,25.163 J1000.18@76.875,25.226
  Int1 (Sign) w0.18: v1(131.343,70.636) 132.11,69.869 v1(132.11,65.869) 132.11,57.201 134.543,54.768 v1(134.543,43.636) 134.543,38.236 131.743,35.436 v1(131.743,32.137)
  Int4 (Sign) w0.18: v1(101.811,31.501) 105.308,31.501 105.943,32.136 120.165,32.136 120.865,31.436 131.042,31.436 v1(131.743,32.137) ; v1(132.11,65.869) v1(187.776,65.869)
  Bottom Layer w0.18: R1019.1@76.875,25.855 76.949,25.781 v1(76.949,24.794)
nFLT2_H2: J16.55 J1001.18 R1020.1 R1034.1 | length 74
  Top Layer w0.18: R1034.1@115.943,73.884 115.968,73.884 116.721,74.636 v1(135.443,74.636) ; v1(132.943,27.636) 132.943,25.987 J1001.18@132.969,25.962
  Top Layer w0.25: J16.55@112.01,73.122 113.729,73.122 114.491,73.884 R1034.1@115.943,73.884
  Top Layer w0.5: v1(132.943,25.936) J1001.18@132.969,25.962
  Int1 (Sign) w0.18: v1(132.943,27.636) 132.943,28.336 135.443,30.836 v1(135.443,74.636)
  Bottom Layer w0.2: R1020.1@132.843,26.036 v1(132.943,25.936)
nFLT2_H3: J16.59 J1002.18 R1021.1 R1036.1 | length 118.5
  Top Layer w0.16: R1036.1@115.943,70.684 115.968,70.684 116.816,69.836 v1(118.843,69.836) ; v1(187.732,28.84) 188.731,27.842 188.731,25.976 188.689,25.934 J1002.18@188.969,25.653
  Top Layer w0.2: v1(188.937,25.169) J1002.18@188.937,25.653
  Top Layer w0.25: J16.59@112.01,72.122 113.545,72.122 114.633,71.034 115.593,71.034 R1036.1@115.943,70.684
  Top Layer w0.5: J1002.18@188.869,26.356 J1002.18@188.902,26.389
  Int1 (Sign) w0.16: v1(185.243,66.436) 186.373,65.306 186.373,50.375 187.081,49.667 187.081,34.099 187.732,33.448 v1(187.732,28.84)
  Int4 (Sign) w0.16: v1(118.843,69.836) 129.099,69.836 132.499,66.436 v1(185.243,66.436)
nFLT2_L: J15.59 J22.7 J1000.31 R1022.2 R1040.2 R1042.2 | length 180.9
  Top Layer w0.18: J1000.31@85.859,21.588 85.859,22.099 85.859,22.616 86.48,23.236 97.708,23.236 v1(98.051,23.58) ; v1(100.843,35.836) v1(115.643,35.836) ; R1042.2@117.543,72.284 117.591,72.236 v1(119.243,72.236) 119.293,72.186 139.193,72.186 v1(139.243,72.136) ; R1040.2@117.543,75.484 117.928,75.869 119.281,75.869 v1(119.347,75.934) ; J15.59@139.233,45.585 v1(139.233,46.704) ; J22.7@188.863,63.816 J22.7@188.993,63.816
  Int1 (Sign) w0.18: v1(119.243,72.236) 119.295,72.288 119.295,75.883 v1(119.347,75.934) ; v1(139.233,46.704) 139.233,53.426 139.806,53.999 v1(139.806,63.32) 139.806,71.573 v1(139.243,72.136)
  Int4 (Sign) w0.18: v1(115.643,35.836) 133.48,35.836 134.58,34.736 v1(138.243,34.736) ; v1(139.806,63.32) 180.891,63.32 181.668,64.096 v1(187.62,64.096)
  Bottom Layer w0.18: R1022.2@86.043,21.236 v1(86.043,22.099) ; v1(98.051,23.58) 98.051,25.038 98.573,25.559 98.573,32.993 100.843,35.264 v1(100.843,35.836) ; v1(138.243,34.736) 138.243,37.536 139.233,38.526 v1(139.233,46.704)
nFLT2_L2: J16.53 J1001.31 R1023.2 R1040.1 | length 86.2
  Top Layer w0.2: v1(110.874,73.641) 110.884,73.632 112,73.632 J16.53@112.01,73.622
  Top Layer w0.25: J16.53@112.01,73.622 113.457,73.622 115.215,75.38 115.839,75.38 R1040.1@115.943,75.484 ; J1001.31@141.759,21.249 J1001.31@141.822,21.313
  Int1 (Sign) w0.18: v1(110.874,73.641) 110.874,72.203 110.155,71.484 110.155,59.514 113.243,56.426 113.243,30.836 118.388,25.691 v1(118.388,21.456)
  Int4 (Sign) w0.18: v1(118.388,21.456) 118.407,21.436 118.958,21.436 119.147,21.248 129.332,21.248 130.435,20.145 133.926,20.145 134.949,21.167 v1@141.605,21.167
  Int4 (Sign) w0.3: v1@141.605,21.167 v1(141.662,21.225)
  Bottom Layer w0.18: R1023.2@141.62,21.183 v1(141.662,21.225)
nFLT2_L3: J16.57 J1002.31 R1024.2 R1042.1 | length 135.5
  Top Layer w0.2: J1002.31@197.842,22.013 v1(197.842,22.028)
  Top Layer w0.25: J16.57@112.511,72.644 112.534,72.622 113.909,72.622 114.247,72.284 v1(115.943,72.284)
  Top Layer w0.5: J1002.31@197.859,21.588 J1002.31@197.859,22.013
  Int1 (Sign) w0.16: v1(197.842,22.028) 198.568,22.753 198.568,27.653 199.043,28.128 199.043,58.922 198.043,59.922 v1(198.043,67.936)
  Int4 (Sign) w0.16: v1(115.943,72.284) 116.591,71.636 136.689,71.636 140.389,67.936 v1(198.043,67.936)
  Bottom Layer w0.2: v1@197.843,22.028 R1024.2@197.843,22.736
  Bottom Layer w0.5: R1024.2@197.859,22.837 R1024.2@197.879,22.857
NTC+_1: C902.1 J101.6 U900.4 | length 5.6
  Bottom Layer w0.2: U900.4@4.45,43.2 4.45,44.65 C902.1@4.6,44.8 4.625,44.8 5.4,45.575 7.257,45.575 7.677,45.155 J101.6@8.08,45.155
NTC-_1: C907.1 J101.1 R902.2 R903.2 | length 8.5
  Bottom Layer w0.2: J101.1@10.92,46.54 10.92,47.795 11.9,48.775 C907.1@11.9,48.8 11.925,48.825 13.841,48.825 R903.2@14,48.984 15.709,48.984 17.1,50.375 R902.2@17.1,50.4
PGD1_12: R1009.1 U1006.1 | length 67
  Top Layer w0.18: v1(149.094,29.786) 149.094,30.412 U1006.1@149.168,30.486
  Int4 (Sign) w0.18: v1(119.106,26.973) 123.426,26.973 125.189,28.736 147.34,28.736 148.39,29.786 v1(149.094,29.786)
  Bottom Layer w0.18: R1009.1@90.043,22.436 90.143,22.336 94.543,22.336 95.123,21.756 98.363,21.756 99.943,23.336 99.943,26.136 103.177,29.37 112.678,29.37 115.075,26.973 v1(119.106,26.973)
PGD2_12: R1006.2 U1006.3 | length 62.6
  Top Layer w0.18: v1(148.043,31.297) 148.043,31.339 148.491,31.786 U1006.3@149.168,31.786
  Int4 (Sign) w0.16: v1(93.943,26.751) 100.558,26.751 104.039,30.232 109.833,30.232 110.301,30.7
  Int4 (Sign) w0.18: 110.301,30.7 147.446,30.7 v1(148.043,31.297)
  Bottom Layer w0.16: R1006.2@88.829,26.999 89.077,26.751 v1(93.943,26.751)
PGD3_12: R1010.1 U1006.6 | length 11.9
  Top Layer w0.18: v1(142.643,29.336) 143.793,30.486 U1006.6@146.918,30.486
  Bottom Layer w0.2: v1(142.643,29.336) 142.643,27.471 142.229,27.057 142.229,23.354 142.403,23.18 142.403,22.818 R1010.1@142.699,22.522
PGD4_12: R1007.2 U1001.1 | length 10.9
  Bottom Layer w0.18: R1007.2@144.829,25.653 149.66,25.653 151.984,27.977 151.984,30.428 152.094,30.538 U1001.1@152.269,30.538
PGD5_12: R1011.1 U1001.3 | length 59
  Int4 (Sign) w0.18: v1(152.343,21.336) 152.743,20.936 171.143,20.936 171.643,20.436 194.043,20.436 194.706,19.774 v1(197.54,19.774)
  Bottom Layer w0.18: U1001.3@152.269,31.838 152.494,31.838 152.884,31.448 152.884,30.11 152.343,29.569 v1(152.343,21.336) ; v1(197.54,19.774) 197.54,20.233 198.079,20.772 198.479,20.772 R1011.1@198.743,21.036
PGD6_12: R1008.2 U1001.6 | length 52.8
  Int3 (GND) w0.5: v1(154.443,29.636) 156.756,29.636 161.127,34.008 v1(161.127,36.352)
  Int4 (Sign) w0.3: v1(161.127,36.352) 162.143,35.336 171.043,35.336 175.743,30.636 190.643,30.636 193.343,27.936 v1(197.643,27.936)
  Bottom Layer w0.3: v1(154.443,29.636) 154.443,30.488 154.493,30.538 U1001.6@154.519,30.538 ; R1008.2@197.543,26.936 197.643,27.036 v1(197.643,27.936)
Pgndin_1: C803.2 C807.2 C808.1 C809.1 C811.1 J10.1 J10.2 J107.3 J108.3 U800.12 U800.13 U800.14 U800.15 U800.16 U801.2 U801.6 | length 3.2
  Top Layer w0.35: C807.2@223.843,93.936 223.848,93.941 223.848,97.107 C809.1@223.853,97.111
PMIC_3V3_OUT_1: J15.28 R103.2 | length 6.3
  Top Layer w0.18: v1(147.229,50.468) 147.233,50.473 J15.28@147.233,51.757
  Bottom Layer w0.18: R103.2@147.223,55.436 147.229,55.431 v1(147.229,50.468)
PMIC_5V0_OUT_1: J15.34 R105.1 | length 110.1
  Top Layer w0.18: J15.34@145.733,51.757 145.738,51.762 145.738,52.931 v1(145.743,52.936) ; v1(240.543,47.636) 241.778,47.636 243.478,45.936 247.793,45.936 R105.1@247.893,46.036
  Int4 (Sign) w0.18: v1(145.743,52.936) 145.743,53.456 146.472,54.185 161.507,54.185 162.555,53.136 186.677,53.136 188.92,50.894 193.801,50.894 196.743,53.836 227.943,53.836 234.143,47.636 v1(240.543,47.636)
PMIC_SAFE_OUT1: J15.32 U1.1 | length 52.6
  Top Layer w0.18: J15.32@146.233,51.757 146.233,50.646 v1(146.243,50.636) ; v1(181.643,49.136) 181.693,49.186 185.393,49.186 v1(185.443,49.236)
  Int4 (Sign) w0.18: v1(146.243,50.636) 146.243,50.036 146.913,49.367 181.328,49.367 181.558,49.136 v1(181.643,49.136) ; v1(185.443,49.236) 187.183,47.497 v1(190.57,47.497)
  Bottom Layer w0.18: U1.1@190.568,52.886 v1(190.57,47.497) v1(190.57,47.497)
